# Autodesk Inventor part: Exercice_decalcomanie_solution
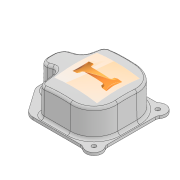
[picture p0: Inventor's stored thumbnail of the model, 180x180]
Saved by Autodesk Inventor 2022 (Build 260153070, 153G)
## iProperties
Created: 2019-12
Part Number: Exercice_decalcomanie_solution
Material: Générique
Document SubType Name: Modeling
Designer: Fabian
Density: 1 g/cm^3
Appearance: Par défaut
Author: Fabian
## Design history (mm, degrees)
sketch "Esquisse1"
  geometry: L1 (0, 70)-(0, -66.117); L2 (90, 0)-(-70, 0); L3 (90, 14.325)-(90, 0); L4 (-70, 45)-(-70, 0); L5 (44.578, 70)-(-45, 70); L6 (86.745, 24.649)-(60.961, 61.472); L7 (83, 0)-(83, 5); L8 (65, 23)-(55, 23); L9 (43, 35)-(43, 51); L10 (31, 63)-(-18, 63); L11 (-63, 18)-(-63, 0); L12 (-63, -18)-(-63, 0); L13 (0, -70)-(0, 66.117); L14 (-70, -45)-(-70, 0); L15 (31, -63)-(-18, -63); L16 (44.578, -70)-(-45, -70); L17 (43, -35)-(43, -51); L18 (90, -14.325)-(90, 0); L19 (86.745, -24.649)-(60.961, -61.472); L20 (83, 0)-(83, -5); L21 (65, -23)-(55, -23); C1 r 4 at (-60, 60); C2 r 6 at (55, 35); C3 r 4 at (-60, -60); C4 r 6 at (55, -35); A1 r 15 centre (-60, 60) between (-51, 72) and (-72, 51); A2 r 12 centre (55, 35) between (43, 35) and (55, 23); A3 r 12 centre (31, 51) between (43, 51) and (31, 63); A4 r 18 centre (72, 14.325) between (90, 14.325) and (86.745, 24.649); A5 r 20 centre (44.578, 50) between (60.961, 61.472) and (44.578, 70); A6 r 10 centre (-45, 80) between (-51, 72) and (-45, 70); A7 r 10 centre (-80, 45) between (-70, 45) and (-72, 51); A8 r 18 centre (65, 5) between (83, 5) and (65, 23); A9 r 45 centre (-18, 18) between (-18, 63) and (-63, 18); A10 r 45 centre (-18, -18) between (-63, -18) and (-18, -63); A11 r 12 centre (31, -51) between (31, -63) and (43, -51); A12 r 10 centre (-45, -80) between (-45, -70) and (-51, -72); A13 r 15 centre (-60, -60) between (-72, -51) and (-51, -72); A14 r 10 centre (-80, -45) between (-72, -51) and (-70, -45); A15 r 12 centre (55, -35) between (55, -23) and (43, -35); A16 r 20 centre (44.578, -50) between (44.578, -70) and (60.961, -61.472); A17 r 18 centre (65, -5) between (65, -23) and (83, -5); A18 r 18 centre (72, -14.325) between (86.745, -24.649) and (90, -14.325); 7 further points
  constraints: 44 end point, 40 point on circle, 32 symmetric about line, 22 centre point, 16 tangent, 14 point on line, 5 perpendicular, 4 coincident, 3 vertical, 2 horizontal, 11 other
  dimensions: "d2" = 70 distance between parallel lines of L4 L1; "d3" = 90 distance between parallel lines of L3 L1; "d5" = 30 diameter of A1; "d6" = 140 diameter of L5 L2; "d7" = 20 distance of point (90, 20) L2.start; "d8" = 35 deg angle of L3 L6; "d9" = 120 diameter of A1.centre L2; "d11" = 60 distance from line of A1.centre L1; "d12" = 8 diameter of C1; "d13" = 70 diameter of C2.centre L2; "d14" = 55 distance from line of C2.centre L1; "d15" = 12 diameter of C2; "d16" = 83 distance between parallel lines of L7 L1; "d17" = 63 distance between parallel lines of L11 L1; "d18" = 46 diameter of L8 L2 (derived); "d19" = 126 diameter of L10 L2; "d21" = 12 radius of A2; "d22" = 43 distance between parallel lines of L9 L1 (derived); "d23" = 12 radius of A3 (derived); "d24" = 18 radius of A4 (derived); "d25" = 20 radius of A5; "d26" = 10 radius of A6; "d27" = 10 radius of A7; "d28" = 18 radius of A8; "d29" = 45 radius of A9
extrude "Extrusion1" new body sketch "Esquisse1" distance "d30" = 65; taper "d31" = -1 deg
sketch "Esquisse2"
  geometry: L1 (-81.865, 65)-(61.865, 65); L2 (0, -455)-(0, 65); L3 (18, 65)-(-31, 65) reference; L4 (-55, 65)-(-65, 65) reference; A1 r 260 centre (0, -195) between (0, -455) and (0, 65); 1 further point
  constraints: 4 end point, 2 point on circle, 1 centre point, 1 collinear, 1 point on line, 1 tangent, 1 vertical, 1 vertical alignment
  dimensions: "d32" = 520 diameter of A1
revolve "Révolution1" sketch "Esquisse2" stored, may be unused: angle "d33" = 90 deg
fillet "Congé1" dims "d36" = 5
feature "Coque1" dims "d37" = 3
extrude "Extrusion2" join sketch "Esquisse1" distance "d34" = 5; taper "d35" = 0 deg
fillet "Congé2" dims "d38" = 5
node "Plan de construction1"
sketch "Esquisse3"
  geometry: L1 (49.281, 43.503)-(49.281, -43.503); L2 (49.281, -43.503)-(-37.725, -43.503); L3 (-37.725, -43.503)-(-37.725, 43.503); L4 (-37.725, 43.503)-(49.281, 43.503); 26 further points; 9 other entities
  constraints: 1 horizontal, 1 horizontal alignment, 1 midpoint, 1 vertical, 19 other
feature "Décalcomanie1" sketch "Esquisse3"
node "Solide1"
node "Image1"
node "Boucle projetée1"
